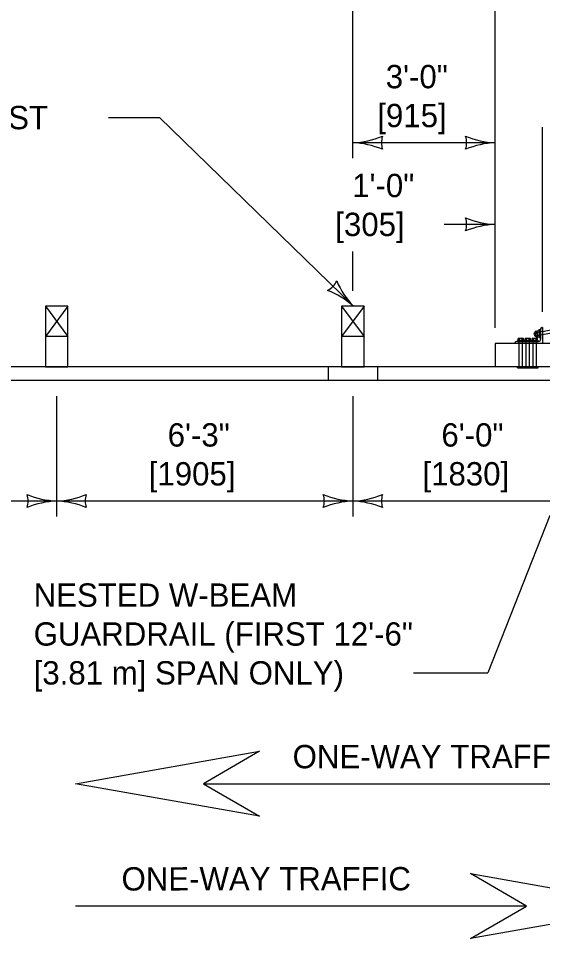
# Model space of a CAD drawing. Extents: x 49991.4 to 50021, y 49987.6 to 50011.4.
# Drawn here: x 50001.42 to 50002.768, y 49995.278 to 49997.645 of the extents above; entities that cross this region are included whole.
import ezdxf

# ---------------------------------------------------------------- set-up
doc = ezdxf.new("R2010")
doc.units = 0
for name, color, linetype in [('Level 1', 7, 'Continuous'), ('Level 2', 7, 'Continuous'), ('Level 3', 7, 'Continuous'), ('Level 4', 7, 'Continuous')]:
    doc.layers.add(name, color=color, linetype=linetype)

msp = doc.modelspace()

# ---------------------------------------------------------------- linework, layer by layer
at = {"layer": 'Level 1'}
for p, q in [((50001.5474, 49996.9044), (50001.4894, 49996.9044)), ((50001.4894, 49996.9044), (50001.4894, 49996.8264)), ((50001.5474, 49996.9044), (50001.4894, 49996.8264)), ((50001.4894, 49996.9044), (50001.5474, 49996.8264)), ((50001.5474, 49996.8264), (50001.5474, 49996.9044)), ((50002.3094, 49996.9044), (50002.2514, 49996.9044)), ((50002.2514, 49996.9044), (50002.2514, 49996.8264)), ((50002.3094, 49996.9044), (50002.2514, 49996.8264)), ((50002.2514, 49996.9044), (50002.3094, 49996.8264)), ((50002.3094, 49996.8264), (50002.3094, 49996.9044)), ((50002.7684, 49996.85), (50002.7671, 49996.85)), ((50002.7684, 49996.8399), (50002.823, 49996.8507)), ((50002.7684, 49996.85), (50002.7684, 49996.8092)), ((50001.4894, 49996.8264), (50001.4894, 49996.7484)), ((50001.5474, 49996.8264), (50001.4894, 49996.8264)), ((50001.5474, 49996.7484), (50001.5474, 49996.8264)), ((50002.2514, 49996.8264), (50002.2514, 49996.7484)), ((50002.3094, 49996.8264), (50002.2514, 49996.8264)), ((50002.3094, 49996.7484), (50002.3094, 49996.8264)), ((50002.7471, 49996.835), (50002.7478, 49996.836)), ((50002.7484, 49996.8285), (50002.7471, 49996.835)), ((50002.7478, 49996.836), (50002.7494, 49996.8363)), ((50002.7478, 49996.836), (50002.7495, 49996.8278)), ((50002.7488, 49996.8297), (50002.7478, 49996.8339)), ((50002.7495, 49996.8278), (50002.7484, 49996.8285)), ((50002.7515, 49996.8259), (50002.7489, 49996.8386)), ((50002.7499, 49996.8298), (50002.7492, 49996.834)), ((50002.7495, 49996.8278), (50002.751, 49996.828)), ((50002.7503, 49996.8407), (50002.7536, 49996.8413)), ((50002.751, 49996.8371), (50002.7541, 49996.8377)), ((50002.7529, 49996.8281), (50002.7553, 49996.8285)), ((50002.7558, 49996.8249), (50002.7536, 49996.8413)), ((50002.7554, 49996.8416), (50002.7589, 49996.842)), ((50002.7559, 49996.838), (50002.7592, 49996.8384)), ((50002.7571, 49996.8288), (50002.7601, 49996.8292)), ((50002.7586, 49996.8449), (50002.7633, 49996.8455)), ((50002.7586, 49996.8449), (50002.7606, 49996.8236)), ((50002.7602, 49996.8451), (50002.7614, 49996.8236)), ((50002.7617, 49996.8453), (50002.7623, 49996.8236)), ((50002.7633, 49996.8462), (50002.7633, 49996.8194)), ((50002.7684, 49996.8317), (50002.8245, 49996.8428)), ((50002.6464, 49996.8092), (50002.6464, 49996.7484)), ((50004.8323, 49996.8092), (50002.6464, 49996.8092)), ((50002.6972, 49996.8092), (50002.6972, 49996.8105)), ((50002.7684, 49996.8092), (50002.6972, 49996.8092)), ((50002.7582, 49996.8143), (50002.701, 49996.8143)), ((50002.704, 49996.8163), (50002.7208, 49996.8163)), ((50002.704, 49996.8163), (50002.704, 49996.8143)), ((50002.704, 49996.8143), (50002.7208, 49996.8143)), ((50002.7056, 49996.8166), (50002.7056, 49996.8215)), ((50002.7073, 49996.8218), (50002.7175, 49996.8218)), ((50002.709, 49996.8166), (50002.709, 49996.8215)), ((50002.7158, 49996.8166), (50002.7158, 49996.8215)), ((50002.7192, 49996.8166), (50002.7192, 49996.8215)), ((50002.7208, 49996.8163), (50002.7208, 49996.8143)), ((50002.722, 49996.8163), (50002.7388, 49996.8163)), ((50002.722, 49996.8163), (50002.722, 49996.8143)), ((50002.722, 49996.8143), (50002.7388, 49996.8143)), ((50002.7236, 49996.8166), (50002.7236, 49996.8215)), ((50002.7253, 49996.8218), (50002.7355, 49996.8218)), ((50002.727, 49996.8166), (50002.727, 49996.8215)), ((50002.7338, 49996.8166), (50002.7338, 49996.8215)), ((50002.7372, 49996.8166), (50002.7372, 49996.8215)), ((50002.7388, 49996.8163), (50002.7388, 49996.8143)), ((50002.74, 49996.8163), (50002.7568, 49996.8163)), ((50002.74, 49996.8163), (50002.74, 49996.8143)), ((50002.74, 49996.8143), (50002.7568, 49996.8143)), ((50002.7416, 49996.8166), (50002.7416, 49996.8215)), ((50002.7433, 49996.8218), (50002.7535, 49996.8218)), ((50002.745, 49996.8166), (50002.745, 49996.8215)), ((50002.7518, 49996.8166), (50002.7518, 49996.8215)), ((50002.7536, 49996.8245), (50002.7558, 49996.8249)), ((50002.7552, 49996.8166), (50002.7552, 49996.8215)), ((50002.7568, 49996.8163), (50002.7568, 49996.8143)), ((50002.7576, 49996.8252), (50002.7604, 49996.8255)), ((50002.7606, 49996.8236), (50002.7633, 49996.8237)), ((50003.8664, 49996.7484), (50000.1363, 49996.7484)), ((50001.4894, 49996.7484), (50001.5474, 49996.7484)), ((50002.2169, 49996.7484), (50002.2169, 49996.7132)), ((50002.2514, 49996.7484), (50002.3094, 49996.7484)), ((50002.3439, 49996.7484), (50002.3439, 49996.7132)), ((50003.9076, 49996.7132), (50000.1529, 49996.7132))]:
    msp.add_line(p, q, dxfattribs=at)
for centre, radius, start, end in [((50002.7671, 49996.8462), 0.0038, 90, 180), ((50002.7507, 49996.8389), 0.00183, 101.1756, 281.1727), ((50002.7569, 49996.8336), 0.00686, 148.8815, 233.6485), ((50002.7533, 49996.8263), 0.00183, 101.1756, 281.1727), ((50002.7556, 49996.8398), 0.00183, 97.6335, 277.6306), ((50002.7614, 49996.834), 0.00679, 144.5965, 230.6676), ((50002.7574, 49996.827), 0.00183, 97.6335, 277.6306), ((50002.701, 49996.8105), 0.0038, 90, 180), ((50002.7582, 49996.8194), 0.00508, 270, 0)]:
    msp.add_arc(centre, radius, start, end, dxfattribs=at)
for centre, major_axis, start_param, end_param in [((50002.7073, 49996.8197), (0.00339, 0), 1.056847, 2.094396), ((50002.7073, 49996.8184), (0.00339, 0), 4.188789, 5.226338), ((50002.7124, 49996.8133), (0.0135, 0), 1.315951, 1.825641), ((50002.7124, 49996.8248), (0.0135, 0), 4.457545, 4.967235), ((50002.7175, 49996.8197), (0.00339, 0), 1.047198, 2.084746), ((50002.7175, 49996.8184), (0.00339, 0), 4.198439, 5.235988), ((50002.7253, 49996.8197), (0.00339, 0), 1.056847, 2.094396), ((50002.7253, 49996.8184), (0.00339, 0), 4.188789, 5.226338), ((50002.7304, 49996.8133), (0.0135, 0), 1.315951, 1.825641), ((50002.7304, 49996.8248), (0.0135, 0), 4.457545, 4.967235), ((50002.7355, 49996.8197), (0.00339, 0), 1.047198, 2.084746), ((50002.7355, 49996.8184), (0.00339, 0), 4.198439, 5.235988), ((50002.7433, 49996.8197), (0.00339, 0), 1.056847, 2.094396), ((50002.7433, 49996.8184), (0.00339, 0), 4.188789, 5.226338), ((50002.7484, 49996.8133), (0.0135, 0), 1.315951, 1.825641), ((50002.7484, 49996.8248), (0.0135, 0), 4.457545, 4.967235), ((50002.7535, 49996.8197), (0.00339, 0), 1.047198, 2.084746), ((50002.7535, 49996.8184), (0.00339, 0), 4.198439, 5.235988)]:
    msp.add_ellipse(centre, major_axis=major_axis, ratio=0.623816, start_param=start_param, end_param=end_param, dxfattribs=at)
at = {"layer": 'Level 3'}
for p, q in [((50002.2804, 49997.2851), (50002.2804, 49998.1412)), ((50002.6464, 49996.8492), (50002.6464, 49997.7042)), ((50001.6515, 49997.3898), (50001.7833, 49997.3898)), ((50002.2816, 49996.9044), (50001.7833, 49997.3898)), ((50002.7684, 49996.89), (50002.7684, 49997.3651)), ((50002.6464, 49997.3251), (50002.2804, 49997.3251)), ((50002.6464, 49997.1151), (50002.5155, 49997.1151)), ((50002.2804, 49996.9444), (50002.2804, 49997.0451)), ((50001.5184, 49996.6732), (50001.5184, 49996.3637)), ((50002.2804, 49996.6732), (50002.2804, 49996.3637)), ((50001.5184, 49996.4037), (50000.7564, 49996.4037)), ((50002.2804, 49996.4037), (50001.5184, 49996.4037)), ((50003.0124, 49996.4037), (50002.2804, 49996.4037)), ((50002.7868, 49996.3665), (50002.6279, 49995.9618)), ((50002.4362, 49995.9618), (50002.6279, 49995.9618)), ((50001.8958, 49995.6766), (50003.0558, 49995.6766)), ((50002.7272, 49995.3622), (50001.5672, 49995.3622))]:
    msp.add_line(p, q, dxfattribs=at)
for points in [[(50002.04, 49995.5932), (50001.5672, 49995.6766), (50002.04, 49995.7604), (50001.8958, 49995.6766)], [(50002.583, 49995.4456), (50003.0558, 49995.3622), (50002.583, 49995.2784), (50002.7272, 49995.3622)]]:
    msp.add_lwpolyline(points, close=True, dxfattribs=at)
for centre, radius, start, end in [((50002.2712, 49997.5472), 0.2223, 272.3605, 292.544), ((50002.2689, 49997.0924), 0.233, 67.9228, 87.1727), ((50002.4086, 49997.3251), 0.0548, 162.1388, 197.8612), ((50002.5182, 49997.3251), 0.0548, 342.1388, 17.8612), ((50002.6579, 49997.5578), 0.233, 247.9228, 267.1727), ((50002.6556, 49997.1029), 0.2223, 92.3605, 112.544), ((50002.5182, 49997.1151), 0.0548, 342.1388, 17.8612), ((50002.6579, 49997.3478), 0.233, 247.9228, 267.1727), ((50002.6556, 49996.8929), 0.2223, 92.3605, 112.544), ((50002.1898, 49996.9939), 0.0548, 297.8921, 333.6145), ((50002.4522, 49997.0631), 0.233, 203.6761, 222.926), ((50002.1332, 49996.7389), 0.2223, 48.1138, 68.2973), ((50001.3902, 49996.4037), 0.0548, 342.1388, 17.8612), ((50001.5299, 49996.6364), 0.233, 247.9228, 267.1727), ((50001.5276, 49996.1815), 0.2223, 92.3605, 112.544), ((50001.5092, 49996.6258), 0.2223, 272.3605, 292.544), ((50001.5069, 49996.171), 0.233, 67.9228, 87.1727), ((50001.6466, 49996.4037), 0.0548, 162.1388, 197.8612), ((50002.1522, 49996.4037), 0.0548, 342.1388, 17.8612), ((50002.2919, 49996.6364), 0.233, 247.9228, 267.1727), ((50002.2896, 49996.1815), 0.2223, 92.3605, 112.544), ((50002.2712, 49996.6258), 0.2223, 272.3605, 292.544), ((50002.2689, 49996.171), 0.233, 67.9228, 87.1727), ((50002.4086, 49996.4037), 0.0548, 162.1388, 197.8612)]:
    msp.add_arc(centre, radius, start, end, dxfattribs=at)
at = {"layer": 'Level 4'}
for p, q in [((50002.7684, 49996.8399), (50002.7505, 49996.8365)), ((50002.7525, 49996.8284), (50002.7684, 49996.8317)), ((50002.7084, 49996.7484), (50002.7084, 49996.8143)), ((50002.7164, 49996.7484), (50002.7164, 49996.8143)), ((50002.7264, 49996.7484), (50002.7264, 49996.8143)), ((50002.7344, 49996.7484), (50002.7344, 49996.8143)), ((50002.7444, 49996.7484), (50002.7444, 49996.8143)), ((50002.7524, 49996.7484), (50002.7524, 49996.8143)), ((50002.704, 49996.7465), (50002.704, 49996.7484)), ((50002.704, 49996.7465), (50002.7208, 49996.7465)), ((50002.7208, 49996.7465), (50002.7208, 49996.7484)), ((50002.722, 49996.7465), (50002.722, 49996.7484)), ((50002.722, 49996.7465), (50002.7388, 49996.7465)), ((50002.7388, 49996.7465), (50002.7388, 49996.7484)), ((50002.74, 49996.7465), (50002.74, 49996.7484)), ((50002.74, 49996.7465), (50002.7568, 49996.7465)), ((50002.7568, 49996.7465), (50002.7568, 49996.7484))]:
    msp.add_line(p, q, dxfattribs=at)

# ---------------------------------------------------------------- texts
at = {"layer": 'Level 2'}
for s, p in [('3\'-0"', (50002.3649, 49997.4651)), ('FIRST W-BEAM POST', (50000.6716, 49997.3598)), ('[915]', (50002.3432, 49997.3651)), ('1\'-0"', (50002.2786, 49997.1851)), ('[305]', (50002.2351, 49997.0851)), ('6\'-3"', (50001.804, 49996.5437)), ('6\'-0"', (50002.5081, 49996.5437)), ('[1905]', (50001.7553, 49996.4437)), ('[1830]', (50002.4594, 49996.4437)), ('NESTED W-BEAM ', (50001.4593, 49996.1318)), ('GUARDRAIL (FIRST 12\'-6"', (50001.4593, 49996.0318)), ('[3.81 m] SPAN ONLY)', (50001.4593, 49995.9318))]:
    msp.add_text(s, height=0.06, dxfattribs=at).set_placement(p)
for p in [(50002.1254, 49995.7164), (50001.6853, 49995.402)]:
    msp.add_text('ONE-WAY TRAFFIC', height=0.06, rotation=0.0331, dxfattribs=at).set_placement(p)

doc.saveas('drawing.dxf')
